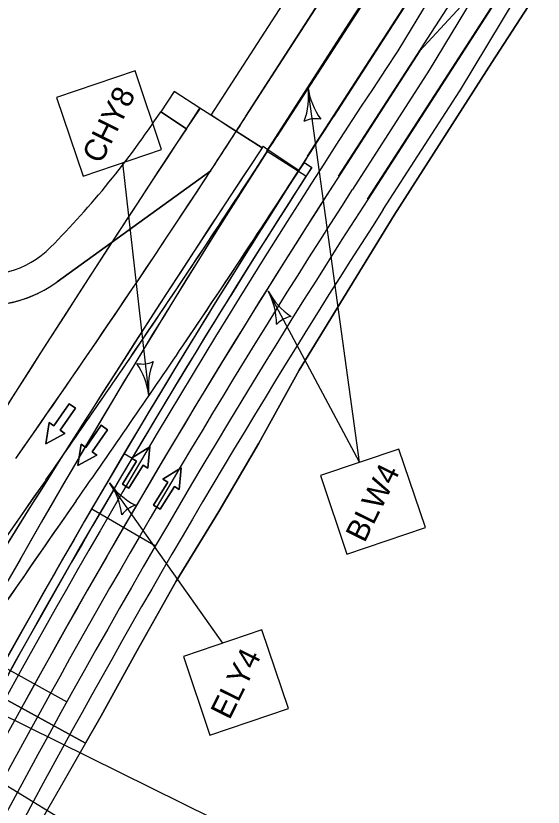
# Model space of a CAD drawing. Extents: x 14104283 to 14120882, y 8635219 to 8671666.
# Drawn here: x 14119080.6 to 14119252.3, y 8668695.1 to 8668952.7 of the extents above; entities that cross this region are included whole.
import ezdxf

# ---------------------------------------------------------------- set-up
doc = ezdxf.new("R2010")
doc.units = 0
for name, color, linetype in [('dsnNonPlotable', 7, 'Continuous'), ('dsnPaintExistingDoubleCenterYellow', 7, 'Continuous'), ('dsnPaintExistingEdgeLineRightWhite', 7, 'Continuous'), ('dsnPaintExistingStopLineWhite', 7, 'Continuous'), ('dsnPaintPlaceBrokenLineWhite', 7, 'Continuous'), ('dsnPaintPlaceEdgeLineLeftYellow', 7, 'Continuous'), ('dsnPaintPlaceEdgeLineRightWhite', 7, 'Continuous'), ('dsnPaintRemoveDoubleCenterLineYellow', 7, 'Continuous'), ('dsnPaintRemoveEdgeLineWhite', 7, 'Continuous'), ('dsnShadingPaved', 7, 'Continuous'), ('dsnStdLabel', 7, 'Continuous'), ('dsnStgShadingPrevPav', 7, 'Continuous'), ('dsnTapePlaceChannelizingLaneWhite', 7, 'Continuous'), ('dsnTapePlaceChannelizingLaneYellow', 7, 'Continuous'), ('dsnTapeRemoveChannelizingWhite', 7, 'Continuous'), ('dsnTapeRemoveDoubleCenterLineYellow', 7, 'Continuous'), ('dsnTextFinalPlan', 7, 'Continuous'), ('Level 2', 7, 'Continuous'), ('Level 5', 7, 'Continuous')]:
    doc.layers.add(name, color=color, linetype=linetype)

msp = doc.modelspace()

# ---------------------------------------------------------------- linework, layer by layer
at = {"layer": 'dsnNonPlotable'}
msp.add_lwpolyline([(14118631.64, 8668945.1), (14119326.37, 8670350.23), (14120231.75, 8669902.59), (14119537.02, 8668497.46)], close=True, dxfattribs=at)
at = {"layer": 'dsnPaintExistingDoubleCenterYellow'}
msp.add_line((14119175.57, 8668906.95), (14119403.44, 8669259.76), dxfattribs=at)
at = {"layer": 'dsnPaintExistingEdgeLineRightWhite'}
msp.add_lwpolyline([(14119412.15, 8669317.07), (14119387.62, 8669279), (14119355.61, 8669229.26), (14119328.75, 8669187.71), (14119296.91, 8669137.95), (14119267.45, 8669092.09), (14119237.9, 8669046.84), (14119206.91, 8668999.35), (14119178.97, 8668956.72), (14119155.37, 8668919.99)], dxfattribs=at)
at = {"layer": 'dsnPaintExistingStopLineWhite'}
for p, q in [((14119105.29, 8668792.23), (14119126.03, 8668780.16)), ((14119076.21, 8668741.04), (14119097.19, 8668729.4))]:
    msp.add_line(p, q, dxfattribs=at)
at = {"layer": 'dsnPaintPlaceBrokenLineWhite'}
msp.add_line((14119185.65, 8668900.44), (14119353.59, 8669160.47), dxfattribs=at)
msp.add_lwpolyline([(14119162.32, 8668908.6), (14119189.03, 8668950.19), (14119216.95, 8668992.78), (14119247.94, 8669040.28), (14119277.52, 8669085.56), (14119307.01, 8669131.47), (14119338.85, 8669181.22), (14119365.7, 8669222.76), (14119397.71, 8669272.51), (14119422.24, 8669310.57)], dxfattribs=at)
for centre, radius, start, end in [((14116224.94, 8670811.47), 3500, 325.95515, 327.15926), ((14121592.11, 8667345.68), 2864.95, 147.15737, 157.1633), ((14116224.94, 8670811.47), 3500, 324.95493, 325.95515), ((14121955.85, 8666791.92), 3500, 144.95493, 149.50762)]:
    msp.add_arc(centre, radius, start, end, dxfattribs=at)
at = {"layer": 'dsnPaintPlaceEdgeLineLeftYellow'}
msp.add_arc((14121592.11, 8667345.68), 2876.95, 147.15737, 151.25989, dxfattribs=at)
at = {"layer": 'dsnPaintPlaceEdgeLineRightWhite'}
for p, q in [((14119195.1, 8668892.97), (14119329.78, 8669101.48)), ((14119144.01, 8668902.22), (14119094.02, 8668866.04))]:
    msp.add_line(p, q, dxfattribs=at)
for centre, radius, start, end in [((14121592.11, 8667345.68), 2852.95, 147.15737, 157.1633), ((14119070.57, 8668898.44), 40, 193.5302, 305.9003)]:
    msp.add_arc(centre, radius, start, end, dxfattribs=at)
at = {"layer": 'dsnPaintRemoveDoubleCenterLineYellow'}
msp.add_line((14119215.15, 8668934.95), (14119190.13, 8668896.18), dxfattribs=at)
msp.add_arc((14121592.11, 8667345.68), 2858.95, 147.15737, 155.63386, dxfattribs=at)
at = {"layer": 'dsnPaintRemoveEdgeLineWhite'}
msp.add_line((14119200.21, 8668889.67), (14119225.14, 8668928.29), dxfattribs=at)
for centre, radius, start, end in [((14121639.53, 8667321.97), 2923.92, 146.37023, 155.59399), ((14121592.11, 8667345.68), 2846.95, 147.15737, 155.63407)]:
    msp.add_arc(centre, radius, start, end, dxfattribs=at)
at = {"layer": 'dsnShadingPaved'}
for p, q in [((14119155.5, 8668919.9), (14119497.22, 8669449.29)), ((14119367.38, 8669159.7), (14119195.17, 8668892.92)), ((14119175.01, 8668905.94), (14119292.62, 8669088.14)), ((14119292.62, 8669088.14), (14119184.06, 8668919.97)), ((14119165.58, 8668913.4), (14119219.81, 8668997.42)), ((14119219.81, 8668997.41), (14119165.58, 8668913.4)), ((14119094.02, 8668866.04), (14119144.01, 8668902.22))]:
    msp.add_line(p, q, dxfattribs=at)
for centre, radius, start, end in [((14116224.94, 8670811.47), 3488, 324.95493, 327.15926), ((14116224.94, 8670811.47), 3512, 325.95515, 327.4129), ((14116224.94, 8670811.47), 3500, 324.95493, 327.15926), ((14116224.94, 8670811.47), 3500, 325.95515, 327.15926), ((14116224.94, 8670811.47), 3512, 325.95515, 327.15926), ((14121592.11, 8667345.68), 2876.95, 147.15737, 157.1633), ((14121592.11, 8667345.68), 2876.95, 147.15737, 151.25989), ((14116224.94, 8670811.47), 3488, 324.95493, 326.81283), ((14121592.11, 8667345.68), 2852.95, 147.15737, 157.1633), ((14119070.57, 8668898.44), 40, 277.2674, 305.9003), ((14116224.94, 8670811.47), 3500, 324.95493, 325.95515), ((14116224.94, 8670811.47), 3512, 324.95493, 325.95515), ((14116224.94, 8670811.47), 3512, 324.95493, 325.95515), ((14121955.85, 8666791.92), 3500, 144.95493, 152.69211), ((14121955.85, 8666791.92), 3500, 144.95493, 149.50762), ((14121955.85, 8666791.92), 3488, 144.95493, 149.50762), ((14121955.85, 8666791.92), 3488, 144.95493, 146.1504)]:
    msp.add_arc(centre, radius, start, end, dxfattribs=at)
at = {"layer": 'dsnStdLabel'}
for p, q in [((14119192.5, 8668807.35), (14119175.68, 8668929.39)), ((14119115.25, 8668904.81), (14119123.87, 8668829.08)), ((14119192.5, 8668807.35), (14119162.74, 8668863.05)), ((14119147.92, 8668748.45), (14119111.08, 8668800.67))]:
    msp.add_line(p, q, dxfattribs=at)
for points in [[(14119102.46, 8668900.48), (14119128.03, 8668909.13), (14119119.38, 8668934.71), (14119093.8, 8668926.06)], [(14119188.37, 8668777.45), (14119213.94, 8668786.1), (14119205.29, 8668811.68), (14119179.72, 8668803.02)], [(14119143.78, 8668718.55), (14119169.36, 8668727.2), (14119160.71, 8668752.78), (14119135.13, 8668744.12)]]:
    msp.add_lwpolyline(points, close=True, dxfattribs=at)
for centre, radius, start, end in [((14119152.94, 8668926.26), 22.95, 339.7797, 7.851), ((14119198.41, 8668932.53), 22.95, 187.8509, 215.9221), ((14119178.3, 8668910.33), 8.86, 80.1167, 115.5851), ((14119142.5, 8668852.24), 22.95, 0.0478, 28.1191), ((14119182.98, 8668873.87), 22.95, 208.1189, 236.1902), ((14119171.81, 8668846.08), 8.86, 100.3848, 135.8532), ((14119121.69, 8668848.2), 8.86, 258.7649, 294.2334), ((14119101.07, 8668826.48), 22.95, 6.4991, 34.5704), ((14119146.67, 8668831.67), 22.95, 158.4279, 186.4993), ((14119092.33, 8668787.44), 22.95, 7.1288, 35.2001), ((14119129.84, 8668813.9), 22.95, 215.2, 243.2713), ((14119122.17, 8668784.95), 8.86, 107.4658, 142.9343)]:
    msp.add_arc(centre, radius, start, end, dxfattribs=at)
at = {"layer": 'dsnStgShadingPrevPav'}
for p, q in [((14119299.05, 8669035.48), (14119212.12, 8668941.29)), ((14119212.08, 8668941.25), (14119185.09, 8668899.43)), ((14119160.76, 8668909.7), (14119140.53, 8668922.62)), ((14119136.09, 8668915.93), (14119127.76, 8668921.44)), ((14119150.62, 8668916.12), (14119144.14, 8668920.3)), ((14119160.72, 8668909.63), (14119150.62, 8668916.12)), ((14119161.09, 8668910.2), (14119162.75, 8668909.09)), ((14119162.76, 8668909.09), (14119172.76, 8668902.45)), ((14119175.01, 8668900.43), (14119162.43, 8668908.54)), ((14119176.88, 8668903.31), (14119174.38, 8668904.97)), ((14119174.4, 8668904.96), (14119176.9, 8668903.3)), ((14119115.84, 8668810.22), (14119118.42, 8668808.69)), ((14119103.24, 8668715.93), (14119074.45, 8668731.78)), ((14119074.5, 8668731.75), (14119103.24, 8668715.93)), ((14119082.38, 8668727.41), (14119103.24, 8668715.93))]:
    msp.add_line(p, q, dxfattribs=at)
for points in [[(14119144.14, 8668920.3), (14119170.94, 8668961.91), (14119198.95, 8669005.04), (14119229.55, 8669052.67), (14119259.7, 8669099.16), (14119288.84, 8669144.53), (14119320.43, 8669193.09), (14119347.13, 8669234.7), (14119379.16, 8669285.01), (14119403.27, 8669322.21)], [(14119455.82, 8669289.13), (14119447.45, 8669266.1), (14119424.62, 8669230.68), (14119396.25, 8669185.73), (14119365.96, 8669139.11), (14119334.97, 8669091.45), (14119304.91, 8669044.51), (14119267.2, 8668986.39), (14119235.59, 8668937.49), (14119203.77, 8668887.79), (14119172.82, 8668837.38)], [(14119172.82, 8668837.38), (14119203.77, 8668887.79), (14119235.59, 8668937.49), (14119267.2, 8668986.39), (14119299.05, 8669035.48)], [(14119172.82, 8668837.38), (14119159.68, 8668813.6), (14119146.7, 8668791.37), (14119132.82, 8668768.69), (14119120.08, 8668746.15), (14119108.33, 8668724.88), (14119103.24, 8668715.93)], [(14119103.24, 8668715.93), (14119108.33, 8668724.88), (14119120.08, 8668746.15), (14119132.82, 8668768.69), (14119146.7, 8668791.37), (14119159.68, 8668813.6), (14119172.82, 8668837.38)], [(14119103.24, 8668715.93), (14119095.89, 8668702.99), (14119082.56, 8668679.77), (14119070.05, 8668656.56), (14119057.76, 8668633.47), (14119046.28, 8668610.93), (14119034.69, 8668587.34), (14119023.78, 8668563.4), (14119013.09, 8668540.14), (14119002.78, 8668517.49), (14118997.49, 8668506.12)]]:
    msp.add_lwpolyline(points, dxfattribs=at)
msp.add_lwpolyline([(14119140.53, 8668922.62), (14119132.12, 8668928.03), (14119127.76, 8668921.44), (14119136.1, 8668915.93)], close=True, dxfattribs=at)
for centre, radius, start, end in [((14123732.96, 8665874.38), 5512, 146.42562, 157.1633), ((14118885.9, 8669081.47), 290, 315.2544, 326.5091), ((14123732.59, 8665873.82), 5512, 146.50213, 150.36196), ((14123732.96, 8665874.38), 5488, 146.42119, 157.1633), ((14121592.11, 8667345.68), 2888.95, 147.23666, 156.23389), ((14123732.85, 8665874.2), 5488.01, 146.41277, 150.66874), ((14121592.11, 8667345.68), 2888.95, 147.23666, 155.3184), ((14121592.13, 8667345.67), 2876.95, 147.18034, 155.90343), ((14121592.11, 8667345.68), 2876.95, 147.18034, 149.39869), ((14121592.11, 8667345.68), 2876.95, 147.24009, 156.23389), ((14121592.13, 8667345.67), 2873.95, 147.18114, 155.90343), ((14121592.11, 8667345.68), 2873.95, 147.18114, 149.39869), ((14121591.75, 8667345.11), 2873.96, 147.23629, 151.15167), ((14121592.11, 8667345.68), 2864.95, 147.15737, 151.16499), ((14119070.57, 8668898.44), 30, 193.5302, 315.2544)]:
    msp.add_arc(centre, radius, start, end, dxfattribs=at)
at = {"layer": 'dsnTapePlaceChannelizingLaneWhite'}
msp.add_arc((14116224.94, 8670811.47), 3488, 326.81283, 327.15926, dxfattribs=at)
at = {"layer": 'dsnTapePlaceChannelizingLaneYellow'}
for centre, radius, start, end in [((14116224.94, 8670811.47), 3512, 325.95515, 327.15926), ((14116224.94, 8670811.47), 3512, 324.95493, 325.95515), ((14121955.85, 8666791.92), 3488, 144.95493, 149.50762)]:
    msp.add_arc(centre, radius, start, end, dxfattribs=at)
at = {"layer": 'dsnTapeRemoveChannelizingWhite'}
for p, q in [((14119224.97, 8668928.03), (14119329.62, 8669101.21)), ((14119298.16, 8669095.5), (14119204.98, 8668941.3))]:
    msp.add_line(p, q, dxfattribs=at)
at = {"layer": 'dsnTapeRemoveDoubleCenterLineYellow'}
msp.add_line((14119308.43, 8669089.29), (14119215.15, 8668934.95), dxfattribs=at)
at = {"layer": 'dsnTextFinalPlan'}
msp.add_line((14118914.55, 8668801.16), (14119143.05, 8668662.37), dxfattribs=at)
at = {"layer": 'Level 2'}
for points in [[(14119099.97, 8668824.96), (14119097.92, 8668826.39), (14119092.92, 8668819.2), (14119091.38, 8668820.28), (14119090.38, 8668813.36), (14119096.51, 8668816.7), (14119094.97, 8668817.78)], [(14119110.4, 8668817.96), (14119108.35, 8668819.39), (14119103.35, 8668812.2), (14119101.81, 8668813.28), (14119100.81, 8668806.36), (14119106.94, 8668809.7), (14119105.4, 8668810.78)], [(14119115.25, 8668800.28), (14119117.37, 8668798.96), (14119121.99, 8668806.39), (14119123.58, 8668805.4), (14119124.22, 8668812.36), (14119118.27, 8668808.7), (14119119.86, 8668807.71)], [(14119125.44, 8668793.41), (14119127.56, 8668792.09), (14119132.18, 8668799.53), (14119133.77, 8668798.54), (14119134.41, 8668805.5), (14119128.46, 8668801.84), (14119130.05, 8668800.85)]]:
    msp.add_lwpolyline(points, close=True, dxfattribs=at)
at = {"layer": 'Level 5'}
for points in [[(14119094.97, 8668817.78), (14119096.51, 8668816.7), (14119090.38, 8668813.36), (14119091.38, 8668820.28), (14119092.92, 8668819.2), (14119097.92, 8668826.39), (14119099.97, 8668824.96), (14119094.97, 8668817.78)], [(14119105.4, 8668810.78), (14119106.94, 8668809.7), (14119100.81, 8668806.36), (14119101.81, 8668813.28), (14119103.35, 8668812.2), (14119108.35, 8668819.39), (14119110.4, 8668817.96), (14119105.4, 8668810.78)], [(14119119.86, 8668807.71), (14119118.27, 8668808.7), (14119124.22, 8668812.36), (14119123.58, 8668805.4), (14119121.99, 8668806.39), (14119117.37, 8668798.96), (14119115.25, 8668800.28), (14119119.86, 8668807.71)], [(14119130.05, 8668800.85), (14119128.46, 8668801.84), (14119134.41, 8668805.5), (14119133.77, 8668798.54), (14119132.18, 8668799.53), (14119127.56, 8668792.09), (14119125.44, 8668793.41), (14119130.05, 8668800.85)]]:
    msp.add_lwpolyline(points, dxfattribs=at)

# ---------------------------------------------------------------- texts
at = {"layer": 'dsnStdLabel'}
for s, p in [('CHY8', (14119108.3, 8668904.17)), ('BLW4', (14119194.1, 8668780.91)), ('ELY4', (14119150.13, 8668723.26))]:
    msp.add_text(s, height=7.2, rotation=63.6912, dxfattribs=at).set_placement(p)

doc.saveas('drawing.dxf')
